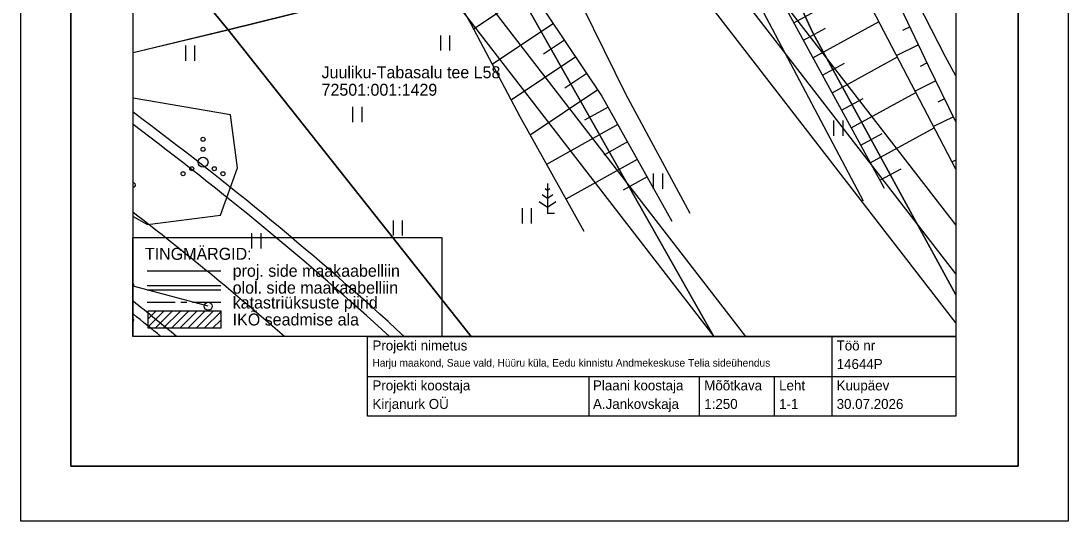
# Model space of a CAD drawing. Extents: x 533279.3 to 533331.8, y 6581483.1 to 6581557.3.
# Drawn here: x 533279.3 to 533331.8, y 6581483.1 to 6581508.1 of the extents above; entities that cross this region are included whole.
import ezdxf

# ---------------------------------------------------------------- set-up
doc = ezdxf.new("R2010")
doc.units = 0
for name, color, linetype in [('HALJASTUS', 7, 'Continuous'), ('PIIR', 7, 'Continuous'), ('POST', 7, 'Continuous'), ('PUU', 7, 'Continuous'), ('RELJEEF', 7, 'Continuous'), ('RP-nõlv', 7, 'Continuous'), ('RP-tee_servajoon', 7, 'Continuous'), ('RP-telg_tee', 7, 'Continuous'), ('TEE', 7, 'Continuous'), ('VORMISTUS', 7, 'Continuous')]:
    doc.layers.add(name, color=color, linetype=linetype)

msp = doc.modelspace()

# ---------------------------------------------------------------- linework, layer by layer
at = {"layer": 'HALJASTUS'}
for p, q in [((533300.322, 6581507.405), (533300.322, 6581506.644)), ((533300.777, 6581507.405), (533300.777, 6581506.644)), ((533287.536, 6581506.899), (533287.536, 6581506.138)), ((533287.991, 6581506.899), (533287.991, 6581506.138)), ((533295.923, 6581503.827), (533295.923, 6581503.066)), ((533296.378, 6581503.827), (533296.378, 6581503.066)), ((533320.04, 6581503.14), (533320.04, 6581502.379)), ((533320.495, 6581503.14), (533320.495, 6581502.379)), ((533310.999, 6581500.48), (533310.999, 6581499.719)), ((533311.454, 6581500.48), (533311.454, 6581499.719)), ((533304.416, 6581498.749), (533304.416, 6581497.988)), ((533304.871, 6581498.749), (533304.871, 6581497.988)), ((533297.954, 6581498.134), (533297.954, 6581497.373)), ((533298.409, 6581498.134), (533298.409, 6581497.373)), ((533290.859, 6581497.492), (533290.859, 6581496.731)), ((533291.314, 6581497.492), (533291.314, 6581496.731))]:
    msp.add_line(p, q, dxfattribs=at)
for points in [[(533290.158, 6581500.776), (533289.806, 6581503.429), (533284.919, 6581504.259)], [(533284.919, 6581498.324), (533285.636, 6581497.932), (533289.291, 6581498.392), (533290.158, 6581500.776)]]:
    msp.add_lwpolyline(points, dxfattribs=at)
for centre, radius in [((533288.424, 6581502.2), 0.1), ((533288.424, 6581501.7), 0.1), ((533287.859, 6581500.725), 0.1), ((533288.424, 6581501.05), 0.25), ((533288.989, 6581500.725), 0.1), ((533287.424, 6581500.475), 0.1), ((533289.424, 6581500.475), 0.1)]:
    msp.add_circle(centre, radius, dxfattribs=at)
msp.add_arc((533284.938, 6581499.908), 0.1, 258.9675, 101.0325, dxfattribs=at)
at = {"layer": 'PIIR'}
for points in [[(533314.039, 6581492.321), (533303.4, 6581511.09), (533294.3, 6581527.13), (533291.41, 6581534.01), (533286.879, 6581544.821)], [(533326.169, 6581494.414), (533319, 6581507.54), (533311.52, 6581523.65), (533302.938, 6581544.821)], [(533302.938, 6581544.821), (533311.52, 6581523.65), (533319, 6581507.54), (533326.169, 6581494.414)], [(533284.919, 6581532.5), (533291.41, 6581534.01), (533294.3, 6581527.13), (533303.4, 6581511.09), (533289.68, 6581507.68), (533284.919, 6581513.462)], [(533284.919, 6581513.462), (533289.68, 6581507.68), (533284.919, 6581506.535)], [(533301.868, 6581492.321), (533289.68, 6581507.68), (533303.4, 6581511.09), (533314.039, 6581492.321)], [(533284.919, 6581506.554), (533289.68, 6581507.68), (533301.868, 6581492.321)]]:
    msp.add_lwpolyline(points, dxfattribs=at)
at = {"layer": 'POST'}
msp.add_line((533288.687, 6581493.833), (533284.919, 6581494.842), dxfattribs=at)
msp.add_circle((533288.687, 6581493.833), 0.2, dxfattribs=at)
for centre, radius, start, end in [((533284.7, 6581494.901), 0.25, 330.8572, 29.1428), ((533284.828, 6581493.14), 0.125, 316.4016, 43.5984), ((533284.828, 6581493.14), 0.105, 329.5408, 30.4592)]:
    msp.add_arc(centre, radius, start, end, dxfattribs=at)
at = {"layer": 'PUU'}
for p, q in [((533305.693, 6581499.986), (533305.693, 6581498.486)), ((533305.693, 6581499.236), (533305.427, 6581499.414)), ((533305.693, 6581499.636), (533305.569, 6581499.719)), ((533305.818, 6581499.719), (533305.693, 6581499.636)), ((533305.96, 6581499.414), (533305.693, 6581499.236)), ((533305.269, 6581499.075), (533305.693, 6581498.792)), ((533305.693, 6581498.792), (533306.117, 6581499.075)), ((533306.053, 6581498.486), (533305.693, 6581498.486))]:
    msp.add_line(p, q, dxfattribs=at)
at = {"layer": 'RELJEEF'}
for p, q in [((533318.043, 6581508.043), (533321.391, 6581509.872)), ((533304.879, 6581509.656), (533301.985, 6581507.715)), ((533305.993, 6581507.995), (533302.928, 6581505.94)), ((533318.523, 6581507.166), (533319.633, 6581507.772)), ((533319.002, 6581506.288), (533322.317, 6581508.099)), ((533323.873, 6581507.831), (533323.495, 6581507.651)), ((533306.55, 6581507.164), (533305.5, 6581506.46)), ((533324.303, 6581506.928), (533323.202, 6581506.404)), ((533307.107, 6581506.334), (533303.872, 6581504.165)), ((533319.961, 6581504.533), (533323.242, 6581506.326)), ((533319.482, 6581505.411), (533320.581, 6581506.011)), ((533324.733, 6581506.025), (533324.377, 6581505.855)), ((533307.664, 6581505.503), (533306.557, 6581504.761)), ((533325.169, 6581505.125), (533324.131, 6581504.619)), ((533308.22, 6581504.672), (533304.833, 6581502.402)), ((533320.92, 6581502.778), (533324.166, 6581504.551)), ((533320.44, 6581503.655), (533321.529, 6581504.25)), ((533325.607, 6581504.226), (533325.269, 6581504.061)), ((533308.733, 6581503.815), (533307.542, 6581503.15)), ((533309.221, 6581502.942), (533305.645, 6581500.945)), ((533326.046, 6581503.327), (533325.053, 6581502.843)), ((533321.399, 6581501.9), (533322.475, 6581502.488)), ((533321.879, 6581501.023), (533325.088, 6581502.776)), ((533309.708, 6581502.069), (533308.516, 6581501.403)), ((533326.169, 6581502.275), (533326.161, 6581502.271)), ((533310.196, 6581501.195), (533306.618, 6581499.198)), ((533326.169, 6581501.162), (533325.975, 6581501.068)), ((533310.683, 6581500.322), (533309.49, 6581499.656)), ((533322.358, 6581500.145), (533323.422, 6581500.726))]:
    msp.add_line(p, q, dxfattribs=at)
for points in [[(533284.919, 6581513.429), (533287.357, 6581513.757), (533292.718, 6581514.44), (533295.532, 6581514.413), (533298.77, 6581513.572), (533302.044, 6581512.29), (533304.781, 6581509.803), (533308.425, 6581504.368), (533311.925, 6581498.098)], [(533326.169, 6581503.075), (533324.818, 6581505.846), (533321.825, 6581512.134), (533320.659, 6581513.322), (533318.883, 6581513.228), (533316.576, 6581511.865), (533317.392, 6581509.235), (533322.569, 6581499.759)], [(533284.919, 6581512.096), (533287.494, 6581512.216), (533293.014, 6581512.587), (533297.606, 6581511.635), (533300.228, 6581510.847), (533301.844, 6581507.98), (533304.308, 6581503.346), (533307.513, 6581497.59)], [(533326.169, 6581500.695), (533323.749, 6581505.354), (533320.405, 6581511.761)]]:
    msp.add_lwpolyline(points, dxfattribs=at)
at = {"layer": 'RP-nõlv'}
msp.add_line((533314.056, 6581492.321), (533284.919, 6581529.994), dxfattribs=at)
for radius, start, end in [(174, 47.52724, 53.33787), (166, 50.63719, 51.25387)]:
    msp.add_arc((533181.024, 6581363.979), radius, start, end, dxfattribs=at)
at = {"layer": 'RP-tee_servajoon'}
for p, q in [((533326.169, 6581493.006), (533286.093, 6581544.821)), ((533326.169, 6581497.91), (533289.885, 6581544.821)), ((533315.637, 6581492.321), (533284.919, 6581532.037))]:
    msp.add_line(p, q, dxfattribs=at)
for radius, start, end in [(173.5, 47.70792, 53.21487), (166.5, 50.4279, 51.39181)]:
    msp.add_arc((533181.024, 6581363.979), radius, start, end, dxfattribs=at)
at = {"layer": 'RP-telg_tee'}
msp.add_line((533326.169, 6581495.458), (533287.989, 6581544.821), dxfattribs=at)
msp.add_arc((533181.024, 6581363.979), 170, 49.02132, 52.3277, dxfattribs=at)
at = {"layer": 'TEE'}
for points in [[(533312.852, 6581498.482), (533309.623, 6581504.459), (533306.388, 6581511.03), (533305.005, 6581512.072), (533302.788, 6581513.446), (533299.515, 6581514.457), (533295.949, 6581515.216), (533292.859, 6581515.08), (533287.545, 6581514.499), (533284.919, 6581514.072)], [(533326.169, 6581505.38), (533325.649, 6581506.325), (533322.502, 6581512.484), (533321.231, 6581515.194), (533318.912, 6581514.304), (533315.616, 6581512.897), (533314.671, 6581512.318), (533316.354, 6581508.865), (533321.528, 6581499.114)]]:
    msp.add_lwpolyline(points, dxfattribs=at)
at = {"layer": 'VORMISTUS'}
for p, q in [((533285.616, 6581495.611), (533289.31, 6581495.611)), ((533285.616, 6581494.877), (533289.31, 6581494.877)), ((533285.616, 6581494.655), (533289.31, 6581494.655)), ((533287.026, 6581494.02), (533285.615, 6581494.02)), ((533287.608, 6581494.02), (533287.317, 6581494.02)), ((533289.31, 6581494.02), (533287.899, 6581494.02)), ((533286.479, 6581493.607), (533285.669, 6581492.797)), ((533286.067, 6581493.607), (533285.669, 6581493.209)), ((533286.891, 6581493.607), (533286.017, 6581492.733)), ((533287.303, 6581493.607), (533286.429, 6581492.733)), ((533287.715, 6581493.607), (533286.841, 6581492.733)), ((533288.126, 6581493.607), (533287.253, 6581492.733)), ((533288.538, 6581493.607), (533287.665, 6581492.733)), ((533288.95, 6581493.607), (533288.076, 6581492.733)), ((533289.31, 6581493.555), (533288.488, 6581492.733)), ((533289.31, 6581493.143), (533288.9, 6581492.733)), ((533319.942, 6581492.321), (533319.942, 6581490.321)), ((533296.669, 6581490.321), (533326.169, 6581490.321)), ((533307.762, 6581490.321), (533307.762, 6581488.321)), ((533313.305, 6581490.321), (533313.305, 6581488.321)), ((533317.058, 6581490.321), (533317.058, 6581488.321)), ((533319.942, 6581490.321), (533319.942, 6581488.321))]:
    msp.add_line(p, q, dxfattribs=at)
for points in [[(533279.294, 6581557.321), (533331.794, 6581557.321), (533331.794, 6581483.071), (533279.294, 6581483.071)], [(533281.794, 6581485.821), (533329.294, 6581485.821), (533329.294, 6581554.571), (533281.794, 6581554.571)], [(533281.794, 6581554.571), (533329.294, 6581554.571), (533329.294, 6581485.821), (533281.794, 6581485.821)], [(533326.169, 6581492.321), (533284.919, 6581492.321), (533284.919, 6581544.821), (533326.169, 6581544.821)], [(533284.91, 6581492.32), (533284.91, 6581497.285), (533300.394, 6581497.285), (533300.394, 6581492.32)], [(533285.669, 6581493.607), (533289.31, 6581493.607), (533289.31, 6581492.733), (533285.669, 6581492.733)], [(533296.669, 6581492.321), (533326.169, 6581492.321), (533326.169, 6581488.321), (533296.669, 6581488.321)]]:
    msp.add_lwpolyline(points, close=True, dxfattribs=at)

# ---------------------------------------------------------------- texts
at = {"layer": 'PIIR'}
for s, p in [('Juuliku-Tabasalu tee L58', (533294.366, 6581505.258)), ('72501:001:1429', (533294.366, 6581504.383))]:
    msp.add_text(s, height=0.6, dxfattribs=at).set_placement(p)
at = {"layer": 'VORMISTUS'}
for s, height, p in [('TINGMÄRGID:', 0.6, (533285.51, 6581496.161)), ('proj. side maakaabelliin', 0.6, (533289.91, 6581495.311)), ('olol. side maakaabelliin', 0.6, (533289.91, 6581494.466)), ('katastriüksuste piirid', 0.6, (533289.91, 6581493.72)), ('IKÕ seadmise ala', 0.6, (533289.91, 6581492.87)), ('Projekti nimetus', 0.5, (533296.918, 6581491.618)), ('Töö nr', 0.5, (533320.191, 6581491.618)), ('Harju maakond, Saue vald, Hüüru küla, Eedu kinnistu Andmekeskuse Telia sideühendus', 0.38, (533296.918, 6581490.809)), ('14644P', 0.5, (533320.191, 6581490.689)), ('Projekti koostaja', 0.5, (533296.918, 6581489.618)), ('Plaani koostaja', 0.5, (533307.975, 6581489.618)), ('Mõõtkava', 0.5, (533313.554, 6581489.618)), ('Leht', 0.5, (533317.307, 6581489.618)), ('Kuupäev', 0.5, (533320.191, 6581489.618)), ('Kirjanurk OÜ', 0.5, (533296.918, 6581488.689)), ('A.Jankovskaja', 0.5, (533307.975, 6581488.689)), ('1:250', 0.5, (533313.554, 6581488.689)), ('1-1', 0.5, (533317.307, 6581488.689)), ('30.07.2026', 0.5, (533320.191, 6581488.689))]:
    msp.add_text(s, height=height, dxfattribs=at).set_placement(p)

doc.saveas('drawing.dxf')
